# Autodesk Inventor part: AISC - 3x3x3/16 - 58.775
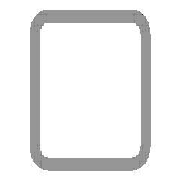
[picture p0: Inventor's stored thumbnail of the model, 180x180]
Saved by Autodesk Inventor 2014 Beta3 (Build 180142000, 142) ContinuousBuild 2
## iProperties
_CCFamilyMember: 9
_CCFamilyDisplayName: ANSI AISC (Square) - Tube
_FrameMemberDoc: Frame Member File
_Version: 15.0.0
_GetPNFromCC: 1
Created: 2011-01
Part Number: AISC - 3x3x3/16 - 58.775
Material: Steel, Mild
Description: Tube
Document SubType Name: Modeling
Standard: ANSI
Designer: Beta-8540w
Standards Organization: ANSI
Language: en-US
Size Designation: 3x3x3/16
Categories: <MemberInstance><Categories><Category DisplayName="Structural Shapes" InternalName="089c4875-fa83-4c05-b084-43b9cc11f5ed" Mnemonic="GRDR"><CategoryParameter Dis
Stock Number: 3x3x3/16
Density: 7.86 g/cm^3
Appearance: Steel
IsCustomPart: 1
G_L: 58.775 in
G_W: 3.000 in
G_H: 3.000 in
+5F3B86C3-FC7A-4F54-B2FE-F4D1CEC6511F+CUTDETAIL1: Cut
Author: Beta-8540w
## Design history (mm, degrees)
node "Start plane"
node "End plane"
sketch "Sketch"
  geometry: L1 (-38.1, -28.575)-(-38.1, 28.575); L2 (-28.575, 38.1)-(28.575, 38.1); L3 (38.1, 28.575)-(38.1, -28.575); L4 (28.575, -38.1)-(-28.575, -38.1); L5 (-28.575, 33.337)-(28.575, 33.338); L6 (33.338, 28.575)-(33.338, -28.575); L7 (28.575, -33.337)-(-28.575, -33.338); L8 (-33.338, -28.575)-(-33.338, 28.575); L9 (0, 56.102)-(0, -56.102) reference; L10 (-56.102, 0)-(56.102, 0) reference; A1 r 9.525 centre (-28.575, -28.575) between (-38.1, -28.575) and (-28.575, -38.1); A2 r 9.525 centre (-28.575, 28.575) between (-28.575, 38.1) and (-38.1, 28.575); A3 r 9.525 centre (28.575, 28.575) between (38.1, 28.575) and (28.575, 38.1); A4 r 9.525 centre (28.575, -28.575) between (28.575, -38.1) and (38.1, -28.575); A5 r 4.763 centre (-28.575, 28.575) between (-28.575, 33.337) and (-33.338, 28.575); A6 r 4.763 centre (28.575, 28.575) between (33.338, 28.575) and (28.575, 33.338); A7 r 4.763 centre (28.575, -28.575) between (28.575, -33.337) and (33.338, -28.575); A8 r 4.763 centre (-28.575, -28.575) between (-33.338, -28.575) and (-28.575, -33.338)
  constraints: 16 end point, 16 point on circle, 8 centre point, 8 tangent, 4 parallel, 3 equal radius, 2 perpendicular, 7 other
  dimensions: "d10" = 76.2 distance between parallel lines of L2 L4 (= G_H); "d11" = 76.2 distance between parallel lines of L1 L3 (= G_W); "d12" = 4.7625 distance between parallel lines of L3 L6 (= G_T); "d15" = 38.1 distance between parallel lines of L2 L10 (= 0.5 x d10); "d16" = 38.1 distance between parallel lines of L9 L3 (= 0.5 x d11); "d17" = 9.525 radius of A1 (= G_IR)
extrude "Body" new body sketch "Sketch" stored distance "d3" = 1492.89148 (= G_L); taper "d4" = 0 deg
node "Driven Length"
  sketch "Sketch3"
    geometry: L1 (0, 0)-(10, 0) reference
    constraints: 2 end point, 1 horizontal
  workplane "Work Plane3"
  sketch "Sketch4"
    geometry: L1 (-2, 0)-(12, 0) reference; L2 (-2, 1492.891)-(12, 1492.891) reference
    dimensions: "d19" = 1492.89148 distance between parallel lines of L1 L2 (derived)
workplane "Work Plane4"
split "Split1"
body "Solid1"
other parameters: "G_W" = 76.2 [user parameter; used in 1 equation term], "G_H" = 76.2 [user parameter; used in 1 equation term], "G_T" = 4.7625 [user parameter; used in 1 equation term], "G_IR" = 9.525 [user parameter; used in 1 equation term], "G_L" = 1492.89148 (= d19) [user parameter; used in 1 equation term], "G_OFFSET_START" = 0 [user parameter; used in 1 equation term], "G_OFFSET_END" = -31.10852 [user parameter; used in 1 equation term], "d13" = 0 (computed from G_OFFSET_START), "d14" = 1492.89148 (= G_OFFSET_END + B_L), "B_L" = 1524 [user parameter; used in 1 equation term], "d18" = 90 deg
